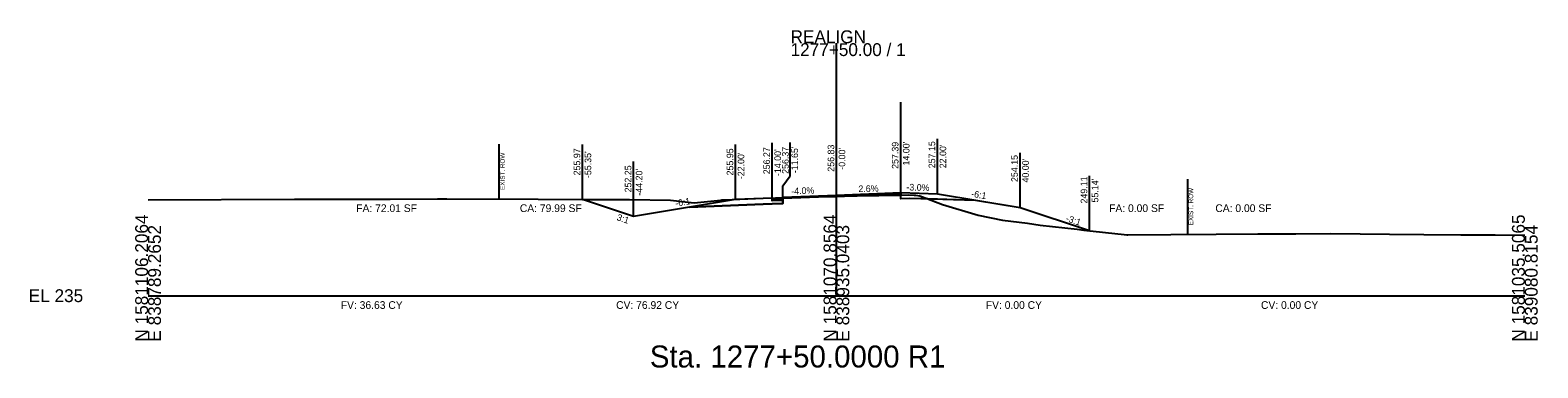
# Model space of a CAD drawing. Extents: x -26 to 6303, y -16 to 9563.
# Drawn here: x 5974.3 to 6302.8, y 1984.3 to 2057.8 of the extents above; entities that cross this region are included whole.
import ezdxf

# ---------------------------------------------------------------- set-up
doc = ezdxf.new("R2010")
doc.units = 0
for name, color, linetype in [('ASPHALT_19MM1', 7, 'Continuous'), ('ASPHALT_9_5MM1', 7, 'Continuous'), ('Default', 7, 'Continuous'), ('Draft_XS_Grid', 7, 'Continuous'), ('Draft_XS_Text', 7, 'Continuous'), ('DTM_TEMP_DROP', 7, 'Continuous'), ('DTM_X_GROUND', 7, 'Continuous'), ('X_TRANS_EOP', 7, 'Continuous'), ('XS_CELL', 7, 'Continuous'), ('XS_M_SHAPES_EARTHWORK', 7, 'Continuous'), ('XS_P_ASPHALT', 7, 'Continuous'), ('XS_P_GROUND', 7, 'Continuous'), ('XS_P_SHOULDER', 7, 'Continuous'), ('XS_P_SUBGRADE_GRANULAR', 7, 'Continuous'), ('XS_P_SUBGRADE_LEVELING', 7, 'Continuous'), ('XS_P_SUBGRADE_MILLING', 7, 'Continuous'), ('XS_P_TX_CLEARZONE', 7, 'Continuous'), ('XS_P_TX_FS_BS', 7, 'Continuous'), ('XS_SHEET_EW_TX_AREA', 7, 'Continuous'), ('XS_SHEET_EW_TX_VOLUME', 7, 'Continuous'), ('XS_X_ROW', 7, 'Continuous')]:
    doc.layers.add(name, color=color, linetype=linetype)

msp = doc.modelspace()

# ---------------------------------------------------------------- linework, layer by layer
at = {"layer": 'ASPHALT_19MM1'}
msp.add_lwpolyline([(6138.35, 2021.03), (6138.35, 2020.76), (6136, 2020.67), (6136, 2020.94), (6138.35, 2021.03)], dxfattribs=at)
at = {"layer": 'ASPHALT_9_5MM1'}
msp.add_lwpolyline([(6138.35, 2021.37), (6138.35, 2021.24), (6136, 2021.15), (6136, 2021.27), (6138.35, 2021.37)], dxfattribs=at)
at = {"layer": 'Default'}
msp.add_lwpolyline([(6138.35, 2021.24), (6138.35, 2021.03), (6136, 2020.94), (6136, 2021.15), (6138.35, 2021.24)], dxfattribs=at)
at = {"layer": 'DTM_X_GROUND'}
msp.add_lwpolyline([(6000, 2020.91), (6031.94, 2021.01), (6050.19, 2021), (6052.72, 2021.01), (6063.1, 2021.07), (6065.13, 2021.08), (6104.88, 2020.93), (6113.82, 2020.83), (6113.84, 2020.83), (6118.97, 2020.21), (6124.8, 2020.84), (6125.06, 2020.87), (6125.62, 2020.89), (6134.05, 2021.21), (6136.72, 2021.31), (6138.35, 2021.37), (6145.68, 2021.54), (6151.79, 2021.67), (6154.5, 2021.73), (6165.67, 2021.96), (6166.92, 2021.92), (6167.33, 2021.89), (6168.14, 2021.76), (6173.08, 2019.85), (6180.85, 2017.57), (6186.2, 2016.48), (6191.61, 2015.83), (6194.36, 2015.38), (6202.48, 2014.46), (6203.88, 2014.24), (6212.68, 2013.31), (6213.31, 2013.27), (6213.47, 2013.27), (6222.83, 2013.33), (6232.75, 2013.39), (6241.8, 2013.45), (6250.11, 2013.5), (6257.74, 2013.55), (6270.52, 2013.37), (6277.96, 2013.33), (6286.07, 2013.28), (6293.57, 2013.24), (6300, 2013.2)], dxfattribs=at)
at = {"layer": 'X_TRANS_EOP'}
msp.add_line((6164, 2022.19), (6164, 2042.19), dxfattribs=at)
at = {"layer": 'XS_CELL'}
for p, q in [((6150, 2000), (6150, 2055)), ((6000, 2000), (6150, 2000)), ((6150, 2000), (6300, 2000))]:
    msp.add_line(p, q, dxfattribs=at)
at = {"layer": 'XS_M_SHAPES_EARTHWORK'}
for points in [[(6094.65, 2020.97), (6104.88, 2020.93), (6113.82, 2020.83), (6113.84, 2020.83), (6118.97, 2020.21), (6124.8, 2020.84), (6125.06, 2020.87), (6125.62, 2020.89), (6134.05, 2021.21), (6136.72, 2021.31), (6138.35, 2021.37), (6145.68, 2021.54), (6145.81, 2021.54), (6145.68, 2021.53), (6138.35, 2021.24), (6138.35, 2021.03), (6138.35, 2020.76), (6138.35, 2020.09), (6136, 2020), (6134, 2019.92), (6117.97, 2019.28), (6105.8, 2017.25)], [(6164, 2021.93), (6165.67, 2021.96), (6166.92, 2021.92), (6167.33, 2021.89), (6168.14, 2021.76), (6169.89, 2021.08), (6166, 2021.2), (6164, 2021.12)], [(6169.89, 2021.08), (6173.08, 2019.85), (6180.85, 2017.57), (6186.2, 2016.48), (6191.61, 2015.83), (6194.36, 2015.38), (6202.48, 2014.46), (6203.88, 2014.24), (6205.14, 2014.11), (6190, 2019.15), (6180.27, 2020.77)]]:
    msp.add_lwpolyline(points, close=True, dxfattribs=at)
at = {"layer": 'XS_P_ASPHALT'}
msp.add_lwpolyline([(6138.35, 2021.24), (6138.35, 2021.24), (6138.35, 2021.24), (6150, 2021.71), (6150, 2021.71), (6164, 2022.27), (6164, 2022.27), (6164, 2022.39), (6150, 2021.83), (6150, 2021.83), (6138.35, 2021.37), (6138.35, 2021.37), (6138.35, 2021.24)], dxfattribs=at)
at = {"layer": 'XS_P_GROUND'}
for points in [[(6128, 2020.95), (6105.8, 2017.25), (6094.65, 2020.97)], [(6205.14, 2014.11), (6205.14, 2014.11), (6190, 2019.15), (6190, 2019.15), (6172, 2022.15)]]:
    msp.add_lwpolyline(points, dxfattribs=at)
at = {"layer": 'XS_P_SHOULDER'}
for points in [[(6136, 2021.27), (6128, 2020.95)], [(6172, 2022.15), (6172, 2022.15), (6164, 2022.39)]]:
    msp.add_lwpolyline(points, dxfattribs=at)
at = {"layer": 'XS_P_SUBGRADE_GRANULAR'}
for points in [[(6138.35, 2020.09), (6138.35, 2021.37)], [(6164, 2021.12), (6164, 2022.39)], [(6180.27, 2020.77), (6180.27, 2020.77), (6166, 2021.2), (6164, 2021.12), (6164, 2021.12)], [(6117.97, 2019.28), (6117.97, 2019.28), (6134, 2019.92), (6134, 2019.92), (6136, 2020)], [(6136, 2020), (6136, 2020), (6138.35, 2020.09)]]:
    msp.add_lwpolyline(points, dxfattribs=at)
at = {"layer": 'XS_P_SUBGRADE_LEVELING'}
msp.add_lwpolyline([(6138.35, 2021.24), (6138.35, 2021.24), (6145.68, 2021.53), (6145.68, 2021.53), (6150, 2021.71), (6150, 2021.71), (6151.79, 2021.78), (6154.5, 2021.89), (6154.5, 2021.89), (6164, 2022.27), (6164, 2022.27), (6164, 2021.93), (6164, 2021.93), (6164, 2021.93), (6154.5, 2021.73), (6154.5, 2021.73), (6151.79, 2021.67), (6150, 2021.63), (6150, 2021.63), (6150, 2021.63), (6145.81, 2021.54), (6145.68, 2021.53), (6145.68, 2021.53), (6138.35, 2021.24), (6138.35, 2021.24)], dxfattribs=at)
at = {"layer": 'XS_P_SUBGRADE_MILLING'}
msp.add_lwpolyline([(6164, 2021.93), (6164, 2021.93), (6154.5, 2021.73), (6154.5, 2021.73), (6151.79, 2021.67), (6150, 2021.63), (6150, 2021.63), (6150, 2021.63), (6145.81, 2021.54), (6145.68, 2021.53), (6145.68, 2021.53), (6138.35, 2021.24), (6138.35, 2021.24), (6138.35, 2021.24), (6138.35, 2021.37), (6138.35, 2021.37), (6145.68, 2021.54), (6145.68, 2021.54), (6150, 2021.63), (6150, 2021.63), (6151.79, 2021.67), (6154.5, 2021.73), (6154.5, 2021.73), (6164, 2021.93), (6164, 2021.93)], dxfattribs=at)
at = {"layer": 'XS_P_TX_CLEARZONE'}
for p, q in [((6150, 2021.83), (6150, 2033.83)), ((6164, 2022.39), (6164, 2034.39)), ((6172, 2022.15), (6172, 2034.15)), ((6094.65, 2020.97), (6094.65, 2032.97)), ((6128, 2020.95), (6128, 2032.95)), ((6136, 2021.27), (6136, 2033.27)), ((6139.92, 2026.12), (6139.92, 2033.37)), ((6190, 2019.15), (6190, 2031.15)), ((6105.8, 2017.25), (6105.8, 2029.25)), ((6138.35, 2023.9), (6139.92, 2026.12)), ((6138.35, 2021.37), (6138.35, 2023.9)), ((6205.14, 2014.11), (6205.14, 2026.11))]:
    msp.add_line(p, q, dxfattribs=at)
at = {"layer": 'XS_X_ROW'}
for p, q in [((6076.53, 2021.03), (6076.53, 2033.03)), ((6226.54, 2013.35), (6226.54, 2025.35))]:
    msp.add_line(p, q, dxfattribs=at)

# ---------------------------------------------------------------- texts
at = {"layer": 'Draft_XS_Grid'}
msp.add_text('-', height=0.0001, dxfattribs=at).set_placement((6000, 2000))
at = {"layer": 'Draft_XS_Text'}
msp.add_text('Sta. 1277+50.0000 R1', height=4.8, dxfattribs=at).set_placement((6109.33, 1984.35))
at = {"layer": 'DTM_TEMP_DROP'}
for p in [(6135.92, 2021.15), (6138.27, 2021.25), (6149.92, 2021.71), (6163.92, 2022.27)]:
    msp.add_text('X', height=0.24, dxfattribs=at).set_placement(p)
at = {"layer": 'X_TRANS_EOP'}
for p in [(6094.58, 2020.85), (6205.06, 2013.99)]:
    msp.add_text('X', height=0.24, dxfattribs=at).set_placement(p)
at = {"layer": 'XS_CELL'}
for s, p in [('REALIGN', (6140, 2055)), ('1277+50.00 / 1', (6140, 2052.2)), ('EL 235', (5974, 1998.6))]:
    msp.add_text(s, height=2.8, dxfattribs=at).set_placement(p)
for s, p in [('N 1581106.2064', (6000, 1990)), ('N 1581070.8564', (6150, 1990)), ('N 1581035.5065', (6300, 1990)), ('E 838789.2652', (6002.8, 1990)), ('E 838935.0403', (6152.8, 1990)), ('E 839080.8154', (6302.8, 1990))]:
    msp.add_text(s, height=2.8, rotation=90, dxfattribs=at).set_placement(p)
at = {"layer": 'XS_P_ASPHALT'}
msp.add_text('X', height=0.24, dxfattribs=at).set_placement((6189.92, 2019.03))
at = {"layer": 'XS_P_SHOULDER'}
for p in [(6127.92, 2020.83), (6171.92, 2022.03)]:
    msp.add_text('X', height=0.24, dxfattribs=at).set_placement(p)
at = {"layer": 'XS_P_SUBGRADE_GRANULAR'}
for p in [(6105.72, 2017.13), (6205.06, 2013.99)]:
    msp.add_text('X', height=0.24, dxfattribs=at).set_placement(p)
at = {"layer": 'XS_P_TX_CLEARZONE'}
for s, p in [('255.97', (6094.17, 2026.21)), ("-55.35'", (6096.57, 2025.62)), ('255.95', (6127.52, 2026.2)), ("-22.00'", (6129.92, 2025.38)), ('256.27', (6135.52, 2026.45)), ("-14.00'", (6137.92, 2026.06)), ('256.37', (6139.6, 2026.54)), ("-11.65'", (6141.63, 2026.68)), ('256.83', (6149.52, 2027.01)), ("-0.00'", (6151.92, 2027.44)), ('257.39', (6163.52, 2027.63)), ("14.00'", (6165.92, 2028.36)), ('257.15', (6171.52, 2027.76)), ("22.00'", (6173.92, 2027.76)), ('254.15', (6189.52, 2024.76)), ('252.25', (6105.32, 2022.5)), ("-44.20'", (6107.72, 2021.79)), ("40.00'", (6191.92, 2024.65)), ('249.11', (6204.66, 2020.08)), ("55.14'", (6207.06, 2020.3))]:
    msp.add_text(s, height=1.44, rotation=90, dxfattribs=at).set_placement(p)
at = {"layer": 'XS_P_TX_FS_BS'}
for s, rotation, p in [('2.6%', 1.4655, (6154.8, 2022.55)), ('-3.0%', 358.2816, (6165.23, 2022.95)), ('-6:1', 9.4642, (6114.98, 2019.39)), ('-4.0%', 2.2906, (6140.18, 2022.04)), ('-6:1', 350.5377, (6179.28, 2021.55)), ('3:1', 341.5668, (6102, 2016.49)), ('-3:1', 341.5651, (6199.86, 2016.27))]:
    msp.add_text(s, height=1.44, rotation=rotation, dxfattribs=at).set_placement(p)
at = {"layer": 'XS_SHEET_EW_TX_AREA'}
for s, p in [('FA: 72.01 SF', (6045.36, 2018.22)), ('CA: 79.99 SF', (6081.01, 2018.22)), ('FA: 0.00 SF', (6209.42, 2018.22)), ('CA: 0.00 SF', (6232.56, 2018.22))]:
    msp.add_text(s, height=1.68, dxfattribs=at).set_placement(p)
at = {"layer": 'XS_SHEET_EW_TX_VOLUME'}
for s, p in [('FV: 36.63 CY', (6041.99, 1997.12)), ('CV: 76.92 CY', (6101.99, 1997.12)), ('FV: 0.00 CY', (6182.55, 1997.12)), ('CV: 0.00 CY', (6242.51, 1997.12))]:
    msp.add_text(s, height=1.68, dxfattribs=at).set_placement(p)
at = {"layer": 'XS_X_ROW'}
for p in [(6077.73, 2023.03), (6227.74, 2015.35)]:
    msp.add_text('EXIST. ROW', height=1, rotation=90, dxfattribs=at).set_placement(p)

doc.saveas('drawing.dxf')
